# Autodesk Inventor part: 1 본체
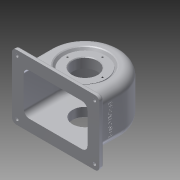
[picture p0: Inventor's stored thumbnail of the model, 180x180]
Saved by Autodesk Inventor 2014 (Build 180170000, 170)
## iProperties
Created: 2015-09
Part Number: 1 본체
Material: 알루미늄 6061
Document SubType Name: Modeling
Designer: aapexcom
Density: 2.71 g/cm^3
Appearance: 알루미늄 - 평지
Mass: 723.768 g
Surface Area: 886.95 cm^2
Volume: 267.073 cm^3
Author: aapexcom
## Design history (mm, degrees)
sketch "스케치1"
  geometry: L1 (63, 52)-(-63, 52); L2 (-70, 45)-(-70, -45); L3 (-63, -52)-(63, -52); L4 (70, -45)-(70, 45); L5 (70, 52)-(-70, -52); L6 (-70, 52)-(70, -52); L7 (68.618, 0)-(-70, 0); L8 (0, -52)-(0, 52); C1 r 2.5 at (62, -44); C2 r 2.5 at (-62, -44); C3 r 2.5 at (62, 44); C4 r 2.5 at (-62, 44); A1 r 7 centre (63, -45) between (63, -52) and (70, -45); A2 r 7 centre (-63, -45) between (-70, -45) and (-63, -52); A3 r 7 centre (-63, 45) between (-63, 52) and (-70, 45); A4 r 7 centre (63, 45) between (70, 45) and (63, 52); 1 further point
  constraints: 16 end point, 8 centre point, 8 point on circle, 8 point on line, 8 tangent, 5 midpoint, 3 equal radius, 2 horizontal, 2 parallel, 1 perpendicular, 1 vertical, 6 other
  dimensions: "d0" = 140 distance of L5.start L6.start; "d1" = 104 distance of L5.end L6.start; "d2" = 5 diameter of C1; "d3" = 8 distance from line of L4 C1.centre; "d4" = 8 distance from line of L3 C1.centre; "d7" = 124 distance of C1.centre C2.centre; "d10" = 88 distance of C1.centre C3.centre; "d13" = 7 radius of A1
extrude "돌출1" new body sketch "스케치1" distance "d14" = 7; taper "d15" = 0 deg
sketch "스케치4"
  geometry: L1 (-70, 0)-(-70, 7) reference; L2 (-70, 7)-(70, 7) reference; L3 (70, 7)-(70, 0) reference; L4 (70, 0)-(-70, 0) reference; L5 (-57, 47)-(-57, 7); L6 (57, 47)-(57, 7); A1 r 57 centre (0, 47) between (57, 47) and (-57, 47); 1 further point
  constraints: 4 end point, 2 perpendicular, 2 point on circle, 2 point on line, 2 tangent, 1 centre point
  dimensions: "d29" = 47 distance of point (0, 0) A1.centre
extrude "돌출2" join sketch "스케치4" stored distance "d31" = 77; taper "d32" = 0 deg
sketch "스케치5"
  geometry: L1 (47, -51.235)-(47, 51.773); L2 (98, -24.5)-(98, 24.5); L3 (89, -33.5)-(67, -33.5); L4 (67, -33.5)-(67, -38.5); L5 (89, 33.5)-(86.747, 33.5); L6 (86.747, 33.5)-(75, 19.5); L7 (75, 19.5)-(67, 19.5); L8 (67, 19.5)-(67, 34.5); L9 (68, 35.5)-(80, 35.5); L10 (80, 35.5)-(80, 34.611); L11 (80.883, 34.29)-(84.416, 38.5); L12 (84.416, 38.5)-(47, 38.5); L13 (67, -38.5)-(47, -38.5); L14 (68, 35.5)-(67, 34.5); L15 (86.747, 33.5)-(67, 33.5); A1 r 9 centre (89, -24.5) between (89, -33.5) and (98, -24.5); A2 r 9 centre (89, 24.5) between (98, 24.5) and (89, 33.5); A3 r 0.5 centre (80.5, 34.611) between (80, 34.611) and (80.883, 34.29); 4 further points
  constraints: 30 end point, 9 point on line, 6 point on circle, 6 tangent, 5 perpendicular, 4 parallel, 3 centre point, 1 equal radius, 1 vertical
  dimensions: "d33" = 47 distance from line of point (0, 0) L1; "d37" = 67 distance of point (98, -33.5) point (98, 33.5); "d38" = 102 diameter of L2 L1; "d41" = 40 diameter of L4 L1; "d42" = 56 diameter of L6.end L1; "d43" = 50 deg angle of L7 L6; "d45" = 40 diameter of L8 L1; "d46" = 66 diameter of L10 L1; "d48" = 5 distance between parallel lines of L6 L11; "d49" = 16 distance of L7.end point (67, 35.5); "d51" = 9 radius of A1; "d52" = 0.5 radius of A3; "d53" = 3 distance between parallel lines of L9 L12; "d54" = 1 distance of L9.start point (67, 35.5); "d55" = 1 distance of L8.end point (67, 35.5) (= d54)
revolve "회전1" stored, may be unused: angle "d56" = 90 deg
chamfer "모따기1" distance "d57" = 1; stored, may be unused: second distance "d58" = 2, angle "d59" = 45 deg
fillet "모깎기1" dims "d60" = 14
sketch "스케치9"
  geometry: L1 (-51, 47)-(-51, 0); L2 (51, 47)-(51, 0); L3 (-51, 0)-(-51, -13.955); L4 (-51, -13.955)-(51, -13.955); L5 (51, -13.955)-(51, 0); A1 r 51 centre (0, 47) between (51, 47) and (-51, 47); 1 further point
  constraints: 10 end point, 3 parallel, 2 point on circle, 2 tangent, 1 centre point, 1 perpendicular, 1 vertical
  dimensions: "d67" = 102 diameter of A1; "d68" = 47 distance of point (0, 0) A1.centre
extrude "돌출3" cut sketch "스케치9" stored distance "d69" = 67; taper "d70" = 0 deg
fillet "모깎기2" dims "d71" = 9
revolve "회전2" stored, may be unused: angle "d72" = 90 deg
sketch "스케치10"
  geometry: C1 r 20 at (0, 47) reference; C2 r 31 at (0, 47); 1 further point
  constraints: 1 centre point, 1 coincident
  dimensions: "d73" = 62 diameter of C2
extrude "돌출4" join sketch "스케치10" distance "d74" = 10; taper "d75" = 0 deg
sketch "스케치11"
  geometry: L1 (-70, 0)-(-70, 7) reference; L2 (-70, 7)-(-57, 7) reference; L3 (-57, 7)-(-57, 47) reference; L4 (57, 47)-(57, 7) reference; L5 (57, 7)-(70, 7) reference; L6 (70, 7)-(70, 0) reference; L7 (70, 0)-(51, 0) reference; L8 (51, 0)-(51, 47) reference; L9 (-51, 47)-(-51, 0) reference; L10 (-51, 0)-(-70, 0) reference; L11 (0, 104)-(0, 110); L12 (0, 110)-(6, 110); L13 (6, 110)-(7.137, 103.551); L14 (6, 110)-(6, 122.205); A1 r 57 centre (0, 47) between (57, 47) and (-57, 47) reference; A2 r 51 centre (0, 47) between (51, 47) and (-51, 47) reference; 1 further point
  constraints: 8 end point, 3 perpendicular, 2 point on circle
  dimensions: "d76" = 6 distance of L11.start L11.end; "d77" = 6 distance of L11.end L12.end; "d78" = 10 deg angle of L14 L13
revolve "회전3" sketch "스케치11" stored, may be unused: angle "d79" = 90 deg
fillet "모깎기3" dims "d80" = 3
sketch "스케치12"
  geometry: C1 r 6 at (0, 0) reference; 1 further point
  constraints: 1 coincident
hole "구멍1" sketch "스케치12" at (0, 0) diameter "d81" = 4.459; stored, may be unused: countersink angle "d85" = 90 deg, drill point angle "d87" = 118 deg; dims "d82" = 12, "d83" = 4, "d84" = 2, "d86" = 12
sketch "스케치13"
  geometry: C1 r 20 at (0, 0) reference; 2 further points
  dimensions: "d88" = 24 distance of point (0, 24) C1.centre
hole "구멍2" sketch "스케치13" at (0, 24) diameter "d89" = 2.459; stored, may be unused: countersink angle "d93" = 90 deg, drill point angle "d95" = 118 deg; dims "d90" = 6, "d91" = 4, "d92" = 2, "d94" = 8
sketch "스케치14"
  geometry: C1 r 33 at (0, 0) reference; 2 further points
  dimensions: "d99" = 28 distance of C1.centre point (0, 28)
hole "구멍3" sketch "스케치14" at (0, 28) diameter "d100" = 2.459; stored, may be unused: countersink angle "d104" = 90 deg, drill point angle "d106" = 118 deg; dims "d101" = 7, "d102" = 4, "d103" = 2, "d105" = 9
fillet "모깎기4" dims "d110" = 3
fillet "모깎기5" dims "d111" = 1
fillet "모깎기6" dims "d112" = 3
chamfer "모따기2" distance "d113" = 1; stored, may be unused: second distance "d114" = 2, angle "d115" = 45 deg
sketch "스케치15"
  geometry: L1 (69.5, -47)-(-20.5, -47) reference; 3 further points
  constraints: 1 midpoint, 1 vertical alignment, 1 other
  dimensions: "d116" = 30 distance from line of L1 point (24.5, -17)
extrude "돌출5" join sketch "스케치15" distance "d117" = 0.5; taper "d118" = 0 deg
node "솔리드1"
pattern_circular "원형 패턴1" dims angle "d97" = 360 deg
pattern_circular "원형 패턴2" dims angle "d108" = 360 deg
node "절단 모서리 투영2"
node "절단 모서리 투영5"
other parameters: "d30" = 114
